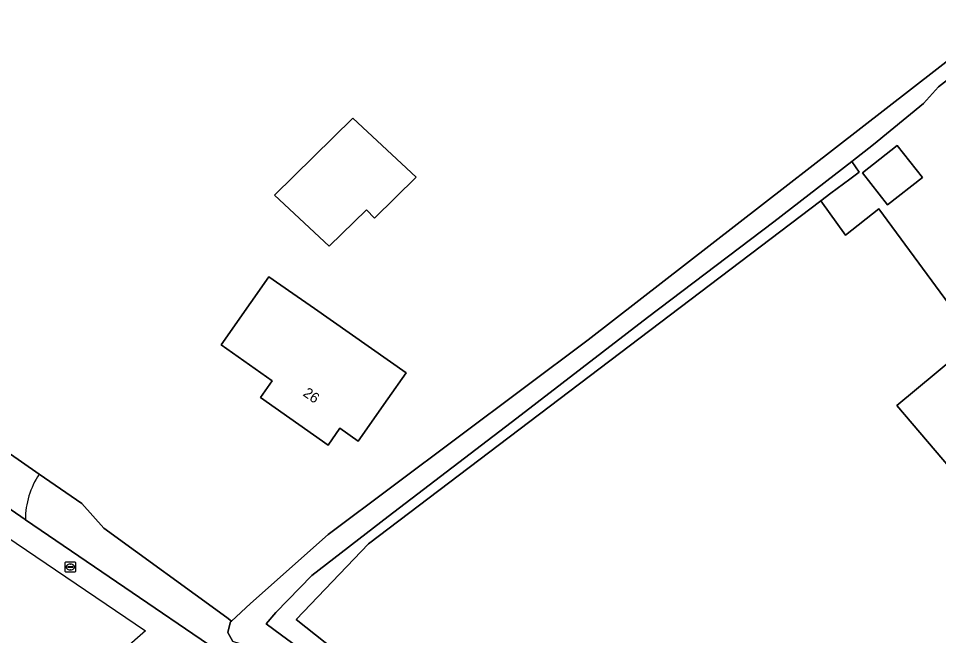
# Model space of a CAD drawing. Extents: x 163859 to 164644, y 379566 to 382155.
# Drawn here: x 164174.8 to 164263.8, y 381867.2 to 381926.9 of the extents above; entities that cross this region are included whole.
import ezdxf

# ---------------------------------------------------------------- set-up
doc = ezdxf.new("R2010")
doc.units = 0
for name, color, linetype in [('IMGEO_Erf', 7, 'Continuous'), ('IMGEO_Grasland_agrarisch', 7, 'Continuous'), ('IMGEO_Grasland_overig', 7, 'Continuous'), ('IMGEO_Groenvoorziening', 7, 'Continuous'), ('IMGEO_Pand', 7, 'Continuous'), ('IMGEO_Pand_nummerreeks', 7, 'Continuous'), ('IMGEO_Rijbaan_lokaal_gesloten', 7, 'Continuous'), ('IMGEO_Rioolput', 7, 'Continuous'), ('IMGEO_Voetpad_open', 7, 'Continuous'), ('IMGEO_Waterloop', 7, 'Continuous')]:
    doc.layers.add(name, color=color, linetype=linetype)

msp = doc.modelspace()

# ---------------------------------------------------------------- linework, layer by layer
at = {"layer": 'IMGEO_Erf'}
for points in [[(164358.416, 382087.209), (164254.852, 381991.262), (164247.66, 381997.032), (164147.193, 381903.339), (164170.551, 381887.103), (164176.8, 381882.795), (164180.902, 381879.968), (164183.031, 381877.576), (164194.945, 381868.909), (164195.394, 381868.583), (164197.248, 381870.262), (164204.736, 381876.958), (164229.912, 381895.792), (164270.687, 381927.48), (164301.861, 381952.134), (164302.429, 381952.58), (164302.08, 381953.025), (164345.159, 381986.829), (164370.617, 381969.688), (164370.447, 381973.615), (164369.98, 381979.405), (164367.666, 382000), (164365.056, 382023.236)], [(164279.852, 381905.358), (164278.809, 381906.762), (164275.938, 381904.422), (164270.874, 381910.635), (164273.813, 381913.03), (164277.667, 381908.3), (164266.944, 381922.737), (164263.797, 381920.285), (164262.336, 381918.681), (164257.521, 381914.686), (164255.409, 381913.055), (164256.122, 381912.023), (164255.217, 381911.353), (164253.39, 381910.001), (164252.396, 381909.265), (164254.791, 381905.941), (164258.029, 381908.469), (164267.387, 381895.767), (164259.755, 381889.448), (164284.619, 381860.24), (164303.691, 381871.549)], [(164209.227, 381907.578), (164208.453, 381908.38), (164204.861, 381904.853), (164199.545, 381909.786), (164207.12, 381917.253), (164213.269, 381911.549)], [(164256.43, 381911.961), (164259.796, 381914.604), (164262.237, 381911.495), (164258.872, 381908.852)], [(164212.28, 381892.593), (164210.522, 381890.091), (164207.647, 381886), (164205.881, 381887.241), (164204.735, 381885.611), (164198.195, 381890.205), (164199.337, 381891.829), (164194.385, 381895.308), (164197.26, 381899.4), (164199.022, 381901.908), (164201.324, 381900.291), (164203.411, 381898.824)]]:
    msp.add_lwpolyline(points, close=True, dxfattribs=at)
at = {"layer": 'IMGEO_Grasland_agrarisch'}
msp.add_lwpolyline([(164303.655, 381951.333), (164266.944, 381922.737), (164277.667, 381908.3), (164278.876, 381906.816), (164278.809, 381906.762), (164279.852, 381905.358), (164303.691, 381871.549), (164284.619, 381860.24), (164259.755, 381889.448), (164267.387, 381895.767), (164258.029, 381908.469), (164254.791, 381905.941), (164252.396, 381909.265), (164208.654, 381876.058), (164201.663, 381868.745), (164211.763, 381860.7), (164222.906, 381852.769), (164256.457, 381829.627), (164286.005, 381809.753), (164322.428, 381783.408), (164335.006, 381775.051), (164338.747, 381777.229), (164392.726, 381806.597)], dxfattribs=at)
at = {"layer": 'IMGEO_Grasland_overig'}
msp.add_lwpolyline([(164211.763, 381860.7), (164201.663, 381868.745), (164208.654, 381876.058), (164252.396, 381909.265), (164253.39, 381910.001), (164255.217, 381911.353), (164256.122, 381912.023), (164255.409, 381913.055), (164247.863, 381907.224), (164235.639, 381897.964), (164222.992, 381888.227), (164210.557, 381878.702), (164203.175, 381872.987), (164199.682, 381869.415), (164198.747, 381868.31), (164200.241, 381867.209), (164203.607, 381864.729)], dxfattribs=at)
at = {"layer": 'IMGEO_Groenvoorziening'}
for points in [[(164261.825, 381821.183), (164221.968, 381849.023), (164223.061, 381850.617), (164219.769, 381853.023), (164219.553, 381852.482), (164219.129, 381851.953), (164218.468, 381851.741), (164217.304, 381852.35), (164212.541, 381855.181), (164205.239, 381860.42), (164197.592, 381866.161), (164196.931, 381866.161), (164195.529, 381866.611), (164195.052, 381867.457), (164195.268, 381868.391), (164195.29, 381868.489), (164195.394, 381868.583), (164194.945, 381868.909), (164183.031, 381877.576), (164180.902, 381879.968), (164176.8, 381882.795)], [(164175.458, 381878.387), (164203.483, 381859.285), (164205.181, 381858.114), (164214.31, 381851.815), (164215.15, 381853.032), (164227.892, 381844.304), (164227.341, 381843.488), (164229.978, 381841.659), (164230.539, 381842.463), (164236.331, 381838.448), (164235.41, 381837.168), (164242.387, 381832.326), (164242.758, 381832.059), (164272.361, 381810.742), (164289.667, 381798.436), (164312.339, 381782.446)]]:
    msp.add_lwpolyline(points, dxfattribs=at)
msp.add_arc((164183.44, 381878.365), 7.982, 146.29071, 179.84392, dxfattribs=at)
at = {"layer": 'IMGEO_Pand'}
for points in [[(164213.269, 381911.549), (164207.12, 381917.253), (164199.545, 381909.786), (164204.861, 381904.853), (164208.453, 381908.38), (164209.227, 381907.578)], [(164256.43, 381911.961), (164258.872, 381908.852), (164262.237, 381911.495), (164259.796, 381914.604)], [(164203.411, 381898.824), (164201.324, 381900.291), (164199.022, 381901.908), (164197.26, 381899.4), (164194.385, 381895.308), (164199.337, 381891.829), (164198.195, 381890.205), (164204.735, 381885.611), (164205.881, 381887.241), (164207.647, 381886), (164210.522, 381890.091), (164212.28, 381892.593)]]:
    msp.add_lwpolyline(points, close=True, dxfattribs=at)
at = {"layer": 'IMGEO_Rijbaan_lokaal_gesloten'}
msp.add_lwpolyline([(164184.975, 381865.791), (164193.85, 381859.772), (164202.562, 381853.773), (164205.181, 381858.114), (164203.483, 381859.285), (164175.458, 381878.387), (164175.446, 381878.395), (164166.649, 381884.443), (164166.499, 381884.544), (164143.584, 381899.974), (164141.791, 381898.302), (164187.087, 381867.645)], close=True, dxfattribs=at)
at = {"layer": 'IMGEO_Rioolput'}
for p, q in [((164179.304, 381873.386), (164179.304, 381874.238)), ((164179.379, 381874.312), (164180.231, 381874.312)), ((164179.792, 381874.092), (164179.817, 381874.092)), ((164180.305, 381874.238), (164180.305, 381873.386)), ((164180.231, 381873.312), (164179.379, 381873.312)), ((164179.563, 381873.806), (164179.563, 381873.818)), ((164180.001, 381873.769), (164179.603, 381873.769)), ((164179.606, 381873.855), (164180.004, 381873.855)), ((164179.815, 381873.532), (164179.79, 381873.532)), ((164180.047, 381873.818), (164180.047, 381873.806))]:
    msp.add_line(p, q, dxfattribs=at)
for points in [[(164179.304, 381873.386), (164179.304, 381874.238)], [(164179.379, 381874.312), (164180.231, 381874.312)], [(164180.305, 381874.238), (164180.305, 381873.386)], [(164180.231, 381873.312), (164179.379, 381873.312)]]:
    msp.add_lwpolyline(points, dxfattribs=at)
for centre, radius, start, end in [((164179.381, 381874.236), 0.0765, 91.55205, 178.44795), ((164179.381, 381874.236), 0.0765, 91.55205, 178.44795), ((164180.229, 381874.236), 0.0765, 1.55205, 88.44795), ((164180.229, 381874.236), 0.0765, 1.55205, 88.44795), ((164179.381, 381873.388), 0.0765, 181.55205, 268.44795), ((164179.381, 381873.388), 0.0765, 181.55205, 268.44795), ((164179.603, 381873.815), 0.0403, 85.87752, 175.75265), ((164179.6, 381873.805), 0.0366, 178.93798, 274.71019), ((164180.004, 381873.812), 0.043, 264.86636, 352.45326), ((164180.008, 381873.817), 0.0386, 1.73085, 96.63898), ((164180.229, 381873.388), 0.0765, 271.55205, 358.44795), ((164180.229, 381873.388), 0.0765, 271.55205, 358.44795)]:
    msp.add_arc(centre, radius, start, end, dxfattribs=at)
for centre, major_axis, ratio, start_param, end_param in [((164179.791, 381873.812), (-0.387, 0.002), 0.722429, 4.712389, 7.853982), ((164179.816, 381873.812), (-0.39, 0.002), 0.717154, 1.570796, 4.712389)]:
    msp.add_ellipse(centre, major_axis=major_axis, ratio=ratio, start_param=start_param, end_param=end_param, dxfattribs=at)
at = {"layer": 'IMGEO_Voetpad_open'}
for points in [[(164176.8, 381882.795), (164170.551, 381887.103)], [(164166.499, 381884.544), (164166.649, 381884.443), (164175.446, 381878.395), (164175.458, 381878.387)]]:
    msp.add_lwpolyline(points, dxfattribs=at)
msp.add_arc((164183.44, 381878.365), 7.982, 146.29071, 179.84392, dxfattribs=at)
at = {"layer": 'IMGEO_Waterloop'}
for points in [[(164270.687, 381927.48), (164229.912, 381895.792), (164204.736, 381876.958), (164197.248, 381870.262), (164195.394, 381868.583), (164195.29, 381868.489), (164195.268, 381868.391), (164195.052, 381867.457), (164195.529, 381866.611)], [(164203.607, 381864.729), (164200.241, 381867.209), (164198.747, 381868.31), (164199.682, 381869.415), (164203.175, 381872.987), (164210.557, 381878.702), (164222.992, 381888.227), (164235.639, 381897.964), (164247.863, 381907.224), (164255.409, 381913.055), (164257.521, 381914.686), (164262.336, 381918.681), (164263.797, 381920.285), (164266.944, 381922.737)]]:
    msp.add_lwpolyline(points, dxfattribs=at)

# ---------------------------------------------------------------- texts
at = {"layer": 'IMGEO_Pand_nummerreeks'}
msp.add_text('26', height=1, rotation=324.91206, dxfattribs=at).set_placement((164202.237, 381890.446))

doc.saveas('drawing.dxf')
